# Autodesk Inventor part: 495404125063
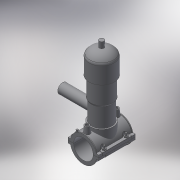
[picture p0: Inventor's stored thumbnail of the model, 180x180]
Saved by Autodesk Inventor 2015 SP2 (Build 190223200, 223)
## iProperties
Created: 2017-07
Part Number: 495404125063
Material: Generic
Description: PLASSON TAPPING VALVE 125-63
Document SubType Name: Modeling
Designer: KIM
Density: 1 g/cm^3
Appearance: Default
Author: KIM
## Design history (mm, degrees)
derived "495404-4954S4.ipt"
feature "Solid1::495404-4954S4.ipt"
feature "Solid2::495404-4954S4.ipt"
tag "TaggingFeature1"
body "Solid1"
body "Solid2"
other parameters: "d0" = 125, "d2" = 162, "d3" = 31.25, "d4" = 118, "d5" = 0, "d6" = 0.1, "d8" = 0, "d19" = 6, "d20" = 6, "d21" = 70.8, "d23" = 0, "d24" = 35.4, "d26" = 0, "d27" = 3, "d28" = 3, "d29" = 3, "d30" = 41.66667, "d31" = 6, "d32" = 0, "d33" = 0, "d34" = 0.6, "d40" = 81.25, "d47" = 129.125, "d70" = 15, "d72" = 0, "d73" = 6, "d75" = 5, "d76" = 0, "d77" = 6.25, "d78" = 92.5, "d79" = 15, "d80" = 47.2, "d82" = 5 deg, "d84" = 4, "d85" = 14, "d86" = 0, "d87" = 3, "d88" = 0, "d89" = 1, "d90" = 1, "d91" = 94.4, "d92" = 0, "d93" = 0.5, "d94" = 65.78947, "d96" = 160.9375, "d97" = 2.36, "d98" = 0, "d120" = 140 deg, "d121" = 24.228, "d122" = 20 deg, "d123" = 312.5, "d124" = 93.75, "d126" = 0, "d143" = 128.75, "d145" = 24.03846, "d149" = 1.875, "d150" = 26.44231, "d153" = 118, "d154" = 0, "d156" = 78.125, "d157" = 160 deg, "d159" = 6.25, "d161" = 1.875, "d162" = 70.8, "d163" = 0, "d164" = 62.5, "d167" = 12.5, "d168" = 76.21951, "d170" = 3, "d172" = 0, "d173" = 1, "d175" = 62.5, "d176" = 20 deg, "d177" = 8.75, "d178" = 31.25, "d180" = 0, "d183" = 12.5, "d184" = 7, "d185" = 38.35, "d186" = 38.35, "d187" = 78.125, "d188" = 9.375, "d189" = 8.75, "d190" = 0, "d191" = 117.1875, "d193" = 6.8, "d194" = 2.95, "d195" = 90 deg, "d197" = 0, "d199" = 0, "d205" = 14.64, "d206" = 81.33333, "d207" = 244, "d208" = 224.48, "d209" = 207.4, "d210" = 200.08, "d211" = 146.4, "d212" = 85.4, "d213" = 65.88, "d214" = 73.2, "d216" = 19.52, "d217" = 70.76, "d218" = 80.52, "d220" = 125, "d222" = 0, "d223" = 156.25, "d224" = 186, "d225" = 51, "d226" = 63, "d229" = 186, "d230" = 0, "d_" = 125, "B_" = 162, "H_" = 186, "L_" = 118, "d_t" = 6, "d_1" = 63, "H_1" = 51, "H_2" = 244, "d148" = 1.875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
